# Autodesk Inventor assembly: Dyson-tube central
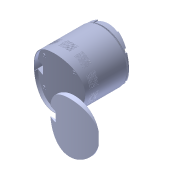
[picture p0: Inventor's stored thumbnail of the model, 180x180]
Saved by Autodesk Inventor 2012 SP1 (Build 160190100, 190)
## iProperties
Created: 2012-11
Part Number: Dyson-tube central
Document SubType Name: Assembly
Designer: Administrateur
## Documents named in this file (6)
- D:\Cours\1-Cours-2013-14\Dropbox\1SI\1. Besoin\Dyson\Composants importés\Dyson Air Multiplier-Assemblage final\Dyson-tube central.iam
- D:\Cours\1-Cours-2013-14\Dropbox\1SI\1. Besoin\Dyson\Composants importés\Dyson Air Multiplier-Assemblage final\Dyson-Partie centre cylindre filtration.ipt
- D:\Cours\1-Cours-2013-14\Dropbox\1SI\1. Besoin\Dyson\Composants importés\Dyson Air Multiplier-Assemblage final\Dyson-Partie centre joint noir.ipt
- D:\Cours\1-Cours-2013-14\Dropbox\1SI\1. Besoin\Dyson\Composants importés\Dyson Air Multiplier-Assemblage final\Dyson-Partie centre cylindre mousse.ipt
- D:\Cours\1-Cours-2013-14\Dropbox\1SI\1. Besoin\Dyson\Composants importés\Dyson Air Multiplier-Assemblage final\Dyson-partie centre motorisation.iam
- D:\Cours\1-Cours-2013-14\Dropbox\1SI\1. Besoin\Dyson\Composants importés\Dyson Air Multiplier-Assemblage final\Dyson-Partie inf. cercle ABS noir.ipt
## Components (5 placed, 5 different names)
1. Dyson-Partie centre cylindre filtration:1 — Placage:1, Placage:2, Placage:3, Placage:4, Placage:5
2. Dyson-Partie centre joint noir:1 — Placage:4, Placage:5
3. Dyson-Partie centre cylindre mousse:1
4. Dyson-partie centre motorisation:1 [sub-assembly]
5. Dyson-Partie inf. cercle ABS noir:1 — Placage:1, Placage:2, Placage:3
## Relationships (5: Mate 5)
- Placage:1 [Mate]: Dyson-Partie centre cylindre filtration:1 ↔ Dyson-Partie inf. cercle ABS noir:1
- Placage:2 [Mate]: Dyson-Partie centre cylindre filtration:1 ↔ Dyson-Partie inf. cercle ABS noir:1
- Placage:3 [Mate]: Dyson-Partie centre cylindre filtration:1 ↔ Dyson-Partie inf. cercle ABS noir:1
- Placage:4 [Mate]: Dyson-Partie centre cylindre filtration:1 ↔ Dyson-Partie centre joint noir:1
- Placage:5 [Mate]: Dyson-Partie centre cylindre filtration:1 ↔ Dyson-Partie centre joint noir:1
